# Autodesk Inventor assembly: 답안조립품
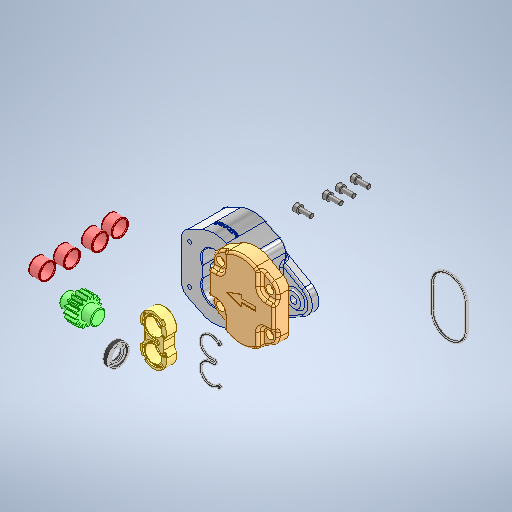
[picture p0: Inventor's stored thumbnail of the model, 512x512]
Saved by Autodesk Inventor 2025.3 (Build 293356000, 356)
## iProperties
Created: 2025-11
Part Number: 답안조립품
Document SubType Name: Assembly
Designer: PC-15
Author: PC-15
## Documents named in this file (11)
- C:\Users\PC-15\Desktop\751103V1011\답안조립품.iam
- C:\Users\PC-15\Desktop\751103V1011\본체.ipt
- C:\Users\PC-15\Desktop\751103V1011\DU 부시\DU 부시\DU 부시.ipt
- C:\Users\PC-15\Desktop\751103V1011\스퍼기어\스퍼기어\스퍼기어.ipt
- C:\Users\PC-15\Desktop\751103V1011\구동기어\구동기어\구동기어.ipt
- C:\Users\PC-15\Desktop\751103V1011\오일 실 16 30 7\오일 실 16 30 7\오일 실 16 30 7.ipt
- C:\Users\PC-15\Desktop\751103V1011\가이드 블록\가이드 블록\가이드 블록.ipt
- C:\Users\PC-15\Desktop\751103V1011\3자 실링\3자 실링\3자 실링.ipt
- C:\Users\PC-15\Desktop\751103V1011\커버\커버\커버.ipt
- C:\Users\PC-15\Desktop\751103V1011\실링\실링\실링.ipt
- C:\Users\PC-15\Desktop\751103V1011\6각 구멍붙이 볼트 M6x16\6각 구멍붙이 볼트 M6x16\6각 구멍붙이 볼트 M6x16.ipt
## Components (11 placed, 5 different names)
1. DU 부시:1
2. DU 부시:2
3. DU 부시:3
4. DU 부시:4
5. 구동기어:1
6. 가이드 블록:1
7. 3자 실링:1
8. 6각 구멍붙이 볼트 M6x16:1
9. 6각 구멍붙이 볼트 M6x16:2
10. 6각 구멍붙이 볼트 M6x16:3
11. 6각 구멍붙이 볼트 M6x16:4
